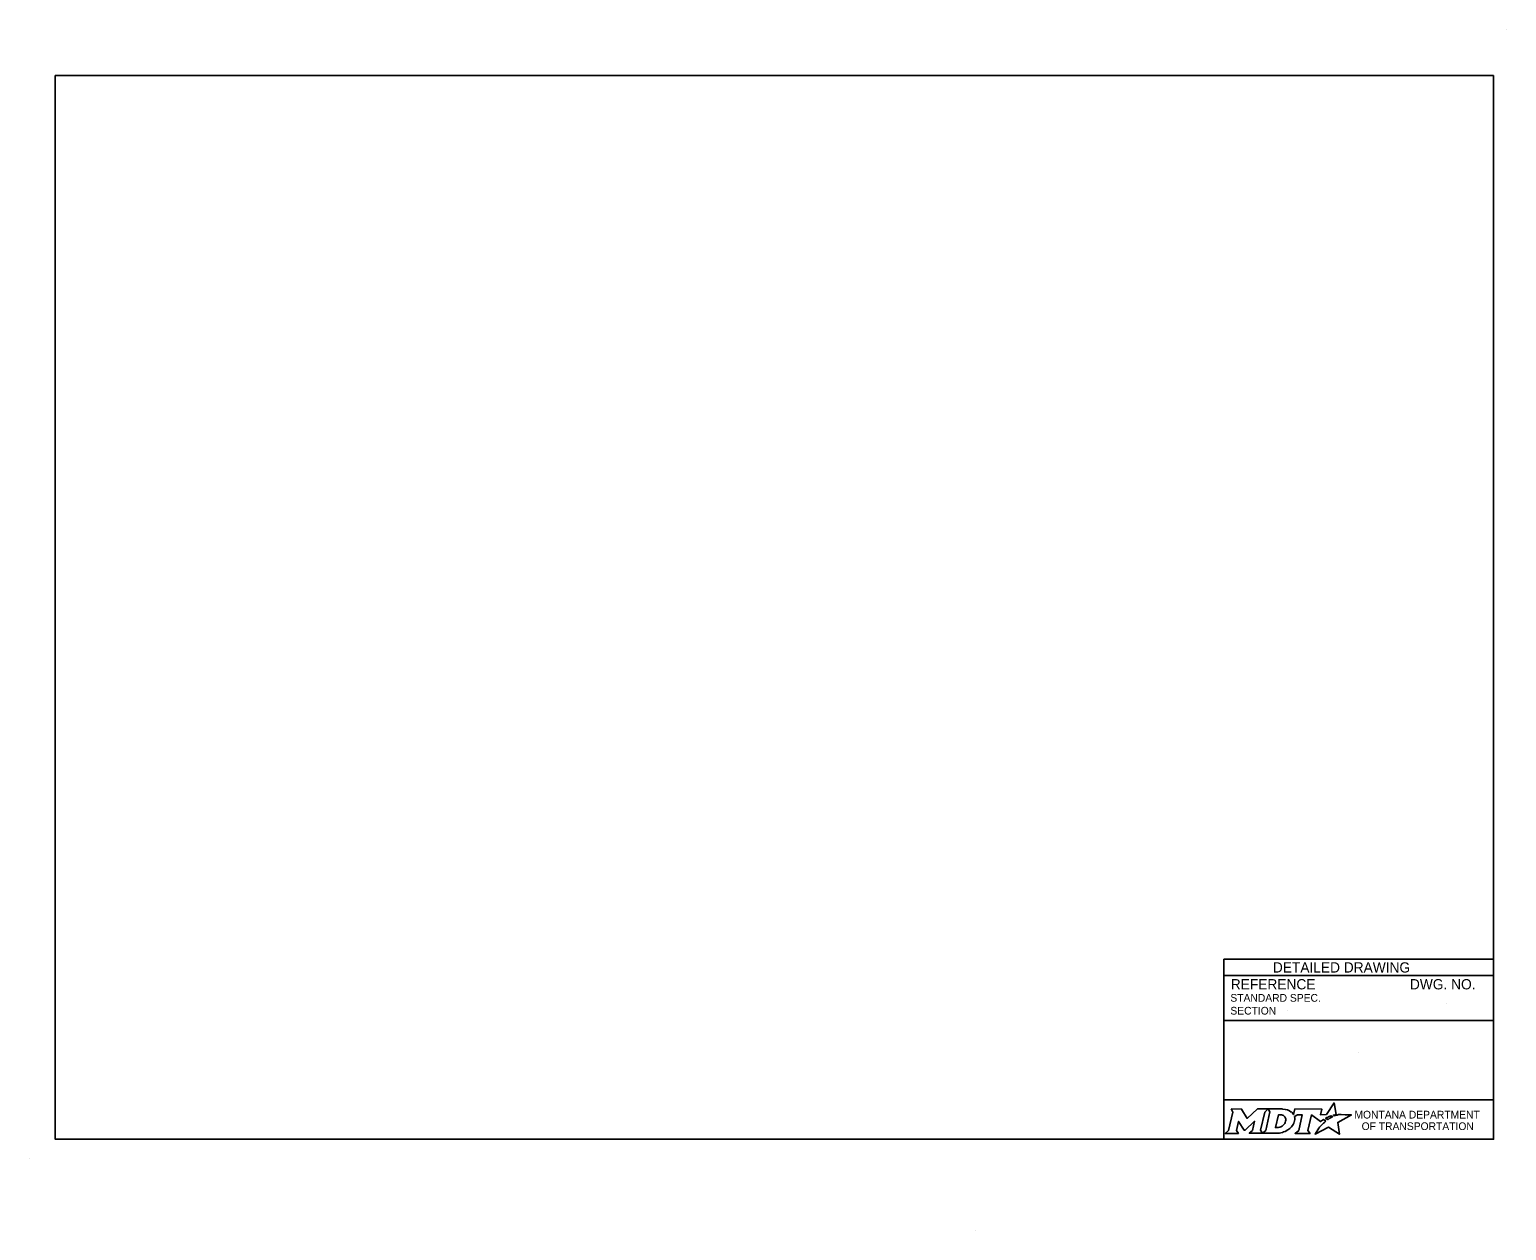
# Model space of a CAD drawing. Extents: x 49991.4 to 50021, y 49987.6 to 50011.4.
# Drawn here: x 50009.54 to 50021.04, y 49999.18 to 50008.52 of the extents above; entities that cross this region are included whole.
import ezdxf

# ---------------------------------------------------------------- set-up
doc = ezdxf.new("R2010")
doc.units = 0
for name, color, linetype in [('Default', 7, 'Continuous'), ('Level 1', 7, 'Continuous'), ('Level 4', 7, 'Continuous')]:
    doc.layers.add(name, color=color, linetype=linetype)

msp = doc.modelspace()

# ---------------------------------------------------------------- linework, layer by layer
at = {"layer": 'Default'}
for points in [[(50018.893, 50000.121), (50018.907, 50000.097), (50018.874, 49999.954), (50018.848, 49999.931), (50018.95, 49999.931), (50018.936, 49999.954), (50018.952, 50000.024), (50018.996, 49999.955), (50019.002, 49999.955), (50019.077, 50000.025), (50019.06, 49999.954), (50019.035, 49999.932), (50019.137, 49999.932), (50019.123, 49999.955), (50019.156, 50000.097)], [(50019.156, 50000.097), (50019.182, 50000.121), (50019.099, 50000.121), (50019.02, 50000.048), (50018.975, 50000.12), (50018.893, 50000.121)], [(50019.295, 50000.121), (50019.182, 50000.121), (50019.196, 50000.098), (50019.163, 49999.954), (50019.137, 49999.932), (50019.248, 49999.932)], [(50019.319, 50000.034), (50019.318, 50000.026), (50019.315, 50000.017), (50019.311, 50000.008), (50019.305, 50000.001), (50019.299, 49999.994), (50019.291, 49999.988), (50019.282, 49999.983), (50019.273, 49999.979), (50019.264, 49999.977), (50019.255, 49999.976), (50019.239, 49999.976), (50019.263, 50000.076), (50019.279, 50000.076), (50019.286, 50000.075), (50019.294, 50000.073), (50019.301, 50000.07), (50019.307, 50000.066), (50019.311, 50000.061), (50019.315, 50000.055), (50019.318, 50000.049), (50019.319, 50000.042), (50019.32, 50000.038), (50019.319, 50000.034)], [(50019.7, 50000.068), (50019.69, 50000.074), (50019.702, 50000.076), (50019.713, 50000.078), (50019.696, 50000.168), (50019.636, 50000.077), (50019.589, 50000.076), (50019.599, 50000.12), (50019.39, 50000.121), (50019.38, 50000.078), (50019.374, 50000.086)], [(50019.387, 50000.062), (50019.411, 50000.075), (50019.448, 50000.075), (50019.42, 49999.954), (50019.392, 49999.931), (50019.508, 49999.931), (50019.491, 49999.954), (50019.52, 50000.075), (50019.591, 50000.023), (50019.612, 50000.038), (50019.632, 50000.027)], [(50019.576, 49999.971), (50019.561, 49999.947), (50019.556, 49999.939), (50019.55, 49999.931), (50019.548, 49999.926), (50019.653, 49999.979), (50019.737, 49999.924), (50019.724, 50000.017), (50019.831, 50000.075), (50019.782, 50000.076), (50019.751, 50000.077), (50019.731, 50000.077), (50019.724, 50000.075), (50019.719, 50000.074), (50019.711, 50000.072), (50019.7, 50000.068)], [(50019.65, 50000.04), (50019.648, 50000.039), (50019.629, 50000.048), (50019.639, 50000.054), (50019.644, 50000.056), (50019.652, 50000.06), (50019.658, 50000.063), (50019.666, 50000.066), (50019.673, 50000.068), (50019.685, 50000.061), (50019.681, 50000.059), (50019.676, 50000.056), (50019.672, 50000.054), (50019.667, 50000.051), (50019.665, 50000.05), (50019.662, 50000.049), (50019.66, 50000.047), (50019.658, 50000.046), (50019.655, 50000.044), (50019.652, 50000.042), (50019.65, 50000.04)], [(50019.293, 49999.939), (50019.302, 49999.942), (50019.315, 49999.947), (50019.335, 49999.958)], [(50019.59, 49999.987), (50019.59, 49999.987)]]:
    msp.add_lwpolyline(points, dxfattribs=at)
for centre, radius, start, end in [((50019.319, 50000.042), 0.0709, 339.5329, 15.8582), ((50019.274, 50000.059), 0.118, 300.9103, 339.1383)]:
    msp.add_arc(centre, radius, start, end, dxfattribs=at)
for centre, major_axis, ratio, start_param, end_param in [((50019.293, 50000.073), (0.0834, -0.0037), 0.568097, 0.61298, 1.570796), ((50019.349, 50000.081), (0.0361, -0.0295), 0.469099, 1.225588, 1.570796), ((50019.583, 49999.979), (-0.00694, -0.00806), 0.008222, 0, 3.137361), ((50019.6, 49999.997), (-0.0098, -0.0102), 0.016458, 3.141593, 6.279097), ((50019.621, 50000.017), (-0.0112, -0.0097), 0.021651, 3.157348, 6.283185), ((50019.248, 50000.08), (0, 0.148), 0.987302, 3.139398, 3.456847)]:
    msp.add_ellipse(centre, major_axis=major_axis, ratio=ratio, start_param=start_param, end_param=end_param, dxfattribs=at)
at = {"layer": 'Level 1'}
for p, q in [((50021.038, 50008.524), (50021.038, 50008.524)), ((50009.537, 49999.736), (50009.537, 49999.736)), ((50016.9, 49999.176), (50016.9, 49999.176))]:
    msp.add_line(p, q, dxfattribs=at)
msp.add_lwpolyline([(50020.938, 50008.165), (50009.737, 50008.165), (50009.737, 49999.886), (50020.938, 49999.886)], close=True, dxfattribs=at)
at = {"layer": 'Level 4'}
for p, q in [((50020.938, 50001.286), (50018.838, 50001.286)), ((50018.838, 50001.286), (50018.838, 49999.886)), ((50020.938, 50001.161), (50018.838, 50001.161)), ((50019.332, 50000.886), (50019.332, 50000.886)), ((50020.574, 50000.946), (50020.574, 50000.946)), ((50020.938, 50000.811), (50018.838, 50000.811)), ((50019.888, 50000.562), (50019.888, 50000.562)), ((50020.938, 50000.193), (50018.838, 50000.193))]:
    msp.add_line(p, q, dxfattribs=at)

# ---------------------------------------------------------------- texts
at = {"layer": 'Default'}
for s, p in [('MONTANA DEPARTMENT', (50019.854, 50000.047)), ('OF TRANSPORTATION', (50019.91, 49999.957))]:
    msp.add_text(s, height=0.06, dxfattribs=at).set_placement(p)
at = {"layer": 'Level 4'}
for s, height, p in [('DETAILED DRAWING', 0.0799, (50019.219, 50001.183)), ('REFERENCE', 0.08, (50018.891, 50001.052)), ('DWG. NO.', 0.08, (50020.286, 50001.052)), ('STANDARD SPEC.', 0.06, (50018.888, 50000.956)), ('SECTION', 0.06, (50018.888, 50000.856))]:
    msp.add_text(s, height=height, dxfattribs=at).set_placement(p)

doc.saveas('drawing.dxf')
